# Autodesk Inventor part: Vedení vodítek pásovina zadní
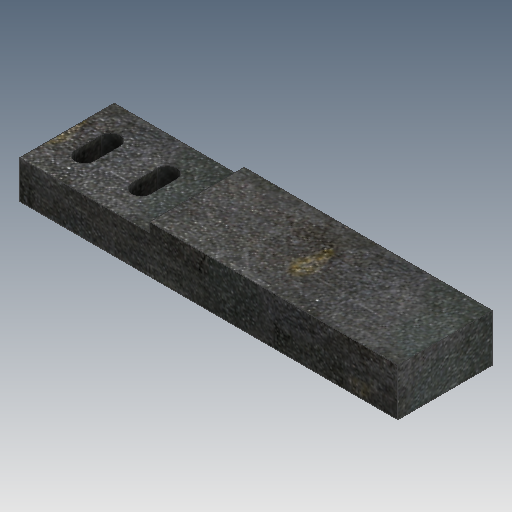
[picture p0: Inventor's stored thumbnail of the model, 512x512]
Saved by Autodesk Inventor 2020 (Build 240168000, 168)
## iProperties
Created: 2025-03
Part Number: Vedení vodítek pásovina zadní
Material: Ocel
Document SubType Name: Modeling
Designer: doma
Density: 7.85 g/cm^3
Appearance: Plech
Mass: 879.677 g
Surface Area: 216.168 cm^2
Volume: 112.061 cm^3
Author: doma
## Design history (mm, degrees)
sketch "Náčrt1"
  geometry: L1 (0, 0)-(0, 16); L2 (0, 16)-(55, 16); L3 (55, 16)-(55, 20); L4 (0, 0)-(160, 0); L5 (160, 0)-(160, 20); L6 (160, 20)-(55, 20)
  constraints: 12 end point, 4 perpendicular, 1 horizontal, 1 vertical
  dimensions: "d0" = 16 distance of L1.start L1.end; "d1" = 55 distance of L1.end L2.end; "d2" = 4 distance of L2.end L3.end; "d3" = 160 distance of L1.start L4.end
extrude "Vysunutí1" new body sketch "Náčrt1" distance "d4" = 40; taper "d5" = 0 deg
sketch "Náčrt2"
  geometry: L1 (0, 0)-(0, -40) reference; L2 (0, -20)-(13, -20); L3 (13, -20)-(37, -20); L4 (13, -25.5)-(13, -14.5); L5 (17, -25.5)-(17, -14.5); L6 (9, -14.5)-(9, -25.5); L7 (37, -25.5)-(37, -14.5); L8 (41, -25.5)-(41, -14.5); L9 (33, -14.5)-(33, -25.5); A1 r 4 centre (13, -25.5) between (9, -25.5) and (17, -25.5); A2 r 4 centre (13, -14.5) between (17, -14.5) and (9, -14.5); A3 r 4 centre (37, -25.5) between (33, -25.5) and (41, -25.5); A4 r 4 centre (37, -14.5) between (41, -14.5) and (33, -14.5)
  constraints: 20 end point, 8 point on circle, 8 tangent, 4 centre point, 3 midpoint, 2 parallel, 2 perpendicular, 1 horizontal, 1 point on line
  dimensions: "d6" = 13 distance of L2.start L2.end; "d7" = 24 distance of L2.end L3.end; "d8" = 5.5 distance of L2.end L4.end; "d9" = 8 diameter of A2; "d10" = 5.5 distance of L3.end L7.end; "d11" = 8 diameter of A4
extrude "Vysunutí2" cut sketch "Náčrt2" distance "d12" = 40; taper "d13" = 0 deg
sketch "Náčrt3"
  geometry: L1 (13, 25.5)-(13, 14.5); L2 (6, 25.5)-(6, 14.5); L3 (20, 14.5)-(20, 25.5); L4 (37, 14.5)-(37, 25.5); L5 (44, 14.5)-(44, 25.5); L6 (30, 25.5)-(30, 14.5); A1 r 4 centre (13, 25.5) between (17, 25.5) and (9, 25.5) reference; A2 r 4 centre (13, 14.5) between (9, 14.5) and (17, 14.5) reference; A3 r 7 centre (13, 25.5) between (20, 25.5) and (6, 25.5); A4 r 7 centre (13, 14.5) between (6, 14.5) and (20, 14.5); A5 r 4 centre (37, 14.5) between (33, 14.5) and (41, 14.5) reference; A6 r 4 centre (37, 25.5) between (41, 25.5) and (33, 25.5) reference; A7 r 7 centre (37, 14.5) between (30, 14.5) and (44, 14.5); A8 r 7 centre (37, 25.5) between (44, 25.5) and (30, 25.5); 3 further points
  constraints: 16 end point, 8 point on circle, 8 tangent, 4 centre point, 3 parallel, 2 midpoint, 1 vertical
  dimensions: "d14" = 14 diameter of A4; "d15" = 14 diameter of A8
extrude "Vysunutí3" cut sketch "Náčrt3" distance "d16" = 8; taper "d17" = 0 deg
node "Těleso1"
